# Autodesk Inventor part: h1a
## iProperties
Created: 2002-02
Part Number: h1a
Document SubType Name: ﾓﾃﾞﾘﾝｸﾞ
Designer: Administrator
Control State: 0
Master: False
Checked Out: False
Shininess: 64.0
Length Units: 11269
Angle Units: 11279
Time Units: 11290
Mass Units: 11284
Length Display Precision: 2
Angle Display Precision: 1
Density: 0.0
Volumn: 0.0
Area: 0.0
PropertySet Name: Model Information
Author: Administrator
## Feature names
1. 派生ﾎﾞﾃﾞｨ1 [Tagging]
